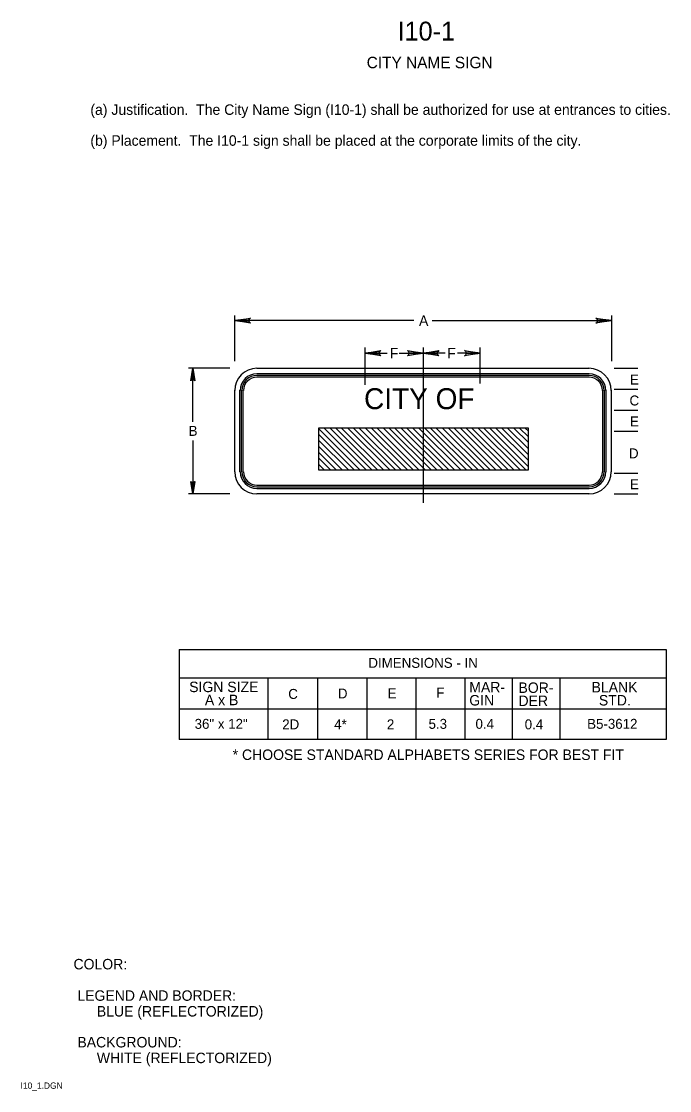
# Model space of a CAD drawing. Extents: x 0.013 to 0.167, y 0.004 to 0.259.
import ezdxf

# ---------------------------------------------------------------- set-up
doc = ezdxf.new("R2010")
doc.units = 0
for name, color, linetype in [('1', 7, 'Continuous'), ('2', 7, 'Continuous'), ('3', 7, 'Continuous')]:
    doc.layers.add(name, color=color, linetype=linetype)

# ---------------------------------------------------------------- blocks, each defined once
blk = doc.blocks.new('RARROW')
at = {"layer": '3'}
for p, q in [((-2.156, 0.285), (-2.2665, 0.384625)), ((-2.2665, 0.384625), (0, 0)), ((0, 0), (-2.2665, -0.379125)), ((-2.156, 0.285), (-2.075625, 0.12075)), ((0, 0), (-2.156, 0.285)), ((-2.14975, -0.2705), (0, 0)), ((-2.075625, 0.12075), (0, 0)), ((0, 0), (-2.074, -0.108)), ((-2.2665, -0.379125), (-2.14975, -0.2705)), ((-2.074, -0.108), (-2.14975, -0.2705))]:
    blk.add_line(p, q, dxfattribs=at)

msp = doc.modelspace()

# ---------------------------------------------------------------- linework, layer by layer
at = {"layer": '1'}
msp.add_line((0.10862, 0.18135), (0.10862, 0.14425), dxfattribs=at)
at = {"layer": '3'}
for p, q in [((0.06363, 0.17804), (0.06363, 0.189)), ((0.15363, 0.17804), (0.15363, 0.189)), ((0.10637, 0.18775), (0.06363, 0.18775)), ((0.11075, 0.18775), (0.15363, 0.18775)), ((0.09475, 0.17245), (0.09475, 0.18134)), ((0.12225, 0.17277), (0.12225, 0.18134)), ((0.09475, 0.17997), (0.1, 0.17997)), ((0.10289, 0.17997), (0.10862, 0.17997)), ((0.10862, 0.18059), (0.10862, 0.17959)), ((0.11388, 0.17997), (0.10862, 0.17997)), ((0.12225, 0.17997), (0.1168, 0.17997)), ((0.06248, 0.17638), (0.05262, 0.17638)), ((0.05362, 0.16362), (0.05362, 0.17638)), ((0.06888, 0.17638), (0.14825, 0.17638)), ((0.15425, 0.17638), (0.15988, 0.17638)), ((0.06888, 0.17513), (0.14825, 0.17513)), ((0.06888, 0.17472), (0.14825, 0.17472)), ((0.06888, 0.17432), (0.14825, 0.17432)), ((0.06363, 0.15163), (0.06363, 0.17112)), ((0.06488, 0.15163), (0.06488, 0.17112)), ((0.06528, 0.15163), (0.06528, 0.17112)), ((0.06567, 0.15163), (0.06567, 0.17112)), ((0.15145, 0.17112), (0.15145, 0.15163)), ((0.15185, 0.17112), (0.15185, 0.15163)), ((0.15225, 0.17112), (0.15225, 0.15163)), ((0.1535, 0.17112), (0.1535, 0.15163)), ((0.15425, 0.17137), (0.15988, 0.17137)), ((0.15425, 0.16637), (0.15988, 0.16637)), ((0.08363, 0.162), (0.0935, 0.15213)), ((0.085, 0.16212), (0.095, 0.15213)), ((0.08638, 0.16212), (0.09638, 0.15213)), ((0.08775, 0.16212), (0.09775, 0.15213)), ((0.08912, 0.16212), (0.09913, 0.15213)), ((0.09062, 0.16212), (0.10063, 0.15213)), ((0.092, 0.16212), (0.102, 0.15213)), ((0.09337, 0.16212), (0.10338, 0.15213)), ((0.09488, 0.16212), (0.10487, 0.15213)), ((0.09625, 0.16212), (0.10625, 0.15213)), ((0.09763, 0.16212), (0.10762, 0.15213)), ((0.09913, 0.16212), (0.10912, 0.15213)), ((0.1005, 0.16212), (0.1105, 0.15213)), ((0.10188, 0.16212), (0.11188, 0.15213)), ((0.10338, 0.16212), (0.11338, 0.15213)), ((0.10475, 0.16212), (0.11475, 0.15213)), ((0.10612, 0.16212), (0.11613, 0.15213)), ((0.10762, 0.16212), (0.11763, 0.15213)), ((0.109, 0.16212), (0.119, 0.15213)), ((0.11038, 0.16212), (0.12037, 0.15213)), ((0.11175, 0.16212), (0.12175, 0.15213)), ((0.11325, 0.16212), (0.12325, 0.15213)), ((0.11463, 0.16212), (0.12462, 0.15213)), ((0.116, 0.16212), (0.126, 0.15213)), ((0.1175, 0.16212), (0.1275, 0.15213)), ((0.11888, 0.16212), (0.12887, 0.15213)), ((0.12025, 0.16212), (0.13025, 0.15213)), ((0.12175, 0.16212), (0.13175, 0.15213)), ((0.12312, 0.16212), (0.13312, 0.15213)), ((0.1245, 0.16212), (0.13375, 0.15288)), ((0.126, 0.16212), (0.13375, 0.15438)), ((0.12738, 0.16212), (0.13375, 0.15575)), ((0.12875, 0.16212), (0.13375, 0.15713)), ((0.13025, 0.16212), (0.13375, 0.15863)), ((0.13162, 0.16212), (0.13375, 0.16)), ((0.133, 0.16212), (0.13375, 0.16137)), ((0.15425, 0.16137), (0.15988, 0.16137)), ((0.05362, 0.15913), (0.05362, 0.14638)), ((0.08363, 0.16062), (0.09212, 0.15213)), ((0.08363, 0.15925), (0.09075, 0.15213)), ((0.08363, 0.15775), (0.08925, 0.15213)), ((0.08363, 0.15638), (0.08788, 0.15213)), ((0.08363, 0.155), (0.0865, 0.15213)), ((0.08363, 0.1535), (0.085, 0.15213)), ((0.08363, 0.15213), (0.08363, 0.15213)), ((0.15425, 0.15138), (0.15988, 0.15138)), ((0.14825, 0.14843), (0.06888, 0.14843)), ((0.06248, 0.14638), (0.05262, 0.14638)), ((0.14825, 0.14803), (0.06888, 0.14803)), ((0.14825, 0.14763), (0.06888, 0.14763)), ((0.14825, 0.14638), (0.06888, 0.14638)), ((0.15425, 0.14638), (0.15988, 0.14638)), ((0.05038, 0.10925), (0.16662, 0.10925)), ((0.05038, 0.10925), (0.05038, 0.08775)), ((0.16662, 0.10925), (0.16662, 0.08775)), ((0.16662, 0.10238), (0.05038, 0.10238)), ((0.07153, 0.10238), (0.07153, 0.08776)), ((0.08338, 0.10238), (0.08338, 0.08775)), ((0.09513, 0.10238), (0.09513, 0.08775)), ((0.10687, 0.10238), (0.10687, 0.08775)), ((0.11853, 0.10238), (0.11853, 0.08776)), ((0.1299, 0.10238), (0.1299, 0.08776)), ((0.14128, 0.10238), (0.14128, 0.08776)), ((0.16662, 0.095), (0.05038, 0.095)), ((0.16662, 0.08775), (0.05038, 0.08775))]:
    msp.add_line(p, q, dxfattribs=at)
msp.add_lwpolyline([(0.13375, 0.16212), (0.08363, 0.16212), (0.08363, 0.15213), (0.13375, 0.15213)], close=True, dxfattribs=at)
for centre, radius, start, end in [((0.06893, 0.17108), 0.0053, 90, 180), ((0.1482, 0.17108), 0.0053, 0, 90), ((0.06893, 0.17108), 0.004, 90, 180), ((0.06893, 0.17108), 0.0036, 90, 180), ((0.06893, 0.17108), 0.0032, 90, 180), ((0.1482, 0.17108), 0.004, 0, 90), ((0.1482, 0.17108), 0.0036, 0, 90), ((0.1482, 0.17108), 0.0032, 0, 90), ((0.06893, 0.15168), 0.0053, 180, 270), ((0.06893, 0.15168), 0.004, 180, 270), ((0.06893, 0.15168), 0.0036, 180, 270), ((0.06893, 0.15168), 0.0032, 180, 270), ((0.1482, 0.15168), 0.0053, 270, 0), ((0.1482, 0.15168), 0.004, 270, 0), ((0.1482, 0.15168), 0.0036, 270, 0), ((0.1482, 0.15168), 0.0032, 270, 0)]:
    msp.add_arc(centre, radius, start, end, dxfattribs=at)

# ---------------------------------------------------------------- block references
for p, xscale, yscale, rotation in [((0.06363, 0.18775), 0.0016545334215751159, 0.0016366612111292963, 180), ((0.09475, 0.17997), 0.0016545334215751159, 0.0016366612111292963, 180), ((0.10862, 0.17997), 0.0016545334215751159, 0.0016366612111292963, 180), ((0.05362, 0.17638), 0.0013236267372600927, 0.001309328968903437, 90), ((0.05362, 0.14638), 0.0013236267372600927, 0.001309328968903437, -90)]:
    msp.add_blockref('RARROW', p, dxfattribs=dict(at, xscale=xscale, yscale=yscale, rotation=rotation))
at = {"layer": '3', "xscale": 0.0016545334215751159, "yscale": 0.0016366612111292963}
for p in [(0.15363, 0.18775), (0.10862, 0.17997), (0.12225, 0.17997)]:
    msp.add_blockref('RARROW', p, dxfattribs=at)

# ---------------------------------------------------------------- texts
at = {"layer": '1'}
for s, height, p in [('I10-1', 0.0045, (0.1025, 0.25462)), ('CITY NAME SIGN', 0.0027503, (0.09513, 0.248)), ('COLOR:', 0.0025, (0.02513, 0.03288)), (' LEGEND AND BORDER:', 0.0024998, (0.02513, 0.02538)), ('      BLUE (REFLECTORIZED)', 0.0024998, (0.02513, 0.02163)), (' BACKGROUND:', 0.0024998, (0.02513, 0.01425)), ('      WHITE (REFLECTORIZED)', 0.0024998, (0.02513, 0.0105)), ('I10_1.DGN', 0.0015, (0.0125, 0.00438))]:
    msp.add_text(s, height=height, dxfattribs=at).set_placement(p)
at = {"layer": '2'}
for s, height, p in [('   (a) Justification.  The City Name Sign (I10-1) shall be authorized for use at entrances to cities.', 0.00249975, (0.02637, 0.23688)), ('   (b) Placement.  The I10-1 sign shall be placed at the corporate limits of the city.', 0.0024998, (0.02637, 0.2295))]:
    msp.add_text(s, height=height, dxfattribs=at).set_placement(p)
at = {"layer": '3'}
for s, height, p in [('A', 0.0025, (0.10762, 0.1865)), ('F', 0.0025, (0.10063, 0.17872)), ('F', 0.0025, (0.11438, 0.17872)), ('E', 0.00238, (0.158, 0.1725)), ('CITY OF', 0.005, (0.0945, 0.16662)), ('C', 0.00238, (0.15788, 0.1675)), ('E', 0.00238, (0.158, 0.1625)), ('B', 0.00238, (0.05262, 0.16025)), ('D', 0.00238, (0.15775, 0.15488)), ('E', 0.00238, (0.158, 0.1475)), ('DIMENSIONS - IN', 0.0023752, (0.09554, 0.10487)), ('SIGN SIZE', 0.0025, (0.05275, 0.09907)), ('C', 0.00238, (0.0764, 0.09745)), ('D', 0.00238, (0.08825, 0.09755)), ('E', 0.00238, (0.10014, 0.0976)), ('F', 0.00238, (0.11175, 0.09775)), ('MAR-', 0.0025, (0.11963, 0.099)), ('BOR-', 0.0025, (0.13137, 0.09888)), ('BLANK', 0.0025, (0.14882, 0.099)), ('A x B', 0.0025, (0.0565, 0.09595)), ('GIN', 0.0025, (0.11963, 0.09588)), ('DER', 0.0025, (0.13137, 0.09575)), ('STD.', 0.0025, (0.15057, 0.09588)), ('36" x 12"', 0.002375, (0.05405, 0.09031)), ('2D', 0.002375, (0.07497, 0.09019)), ('4*', 0.002375, (0.08737, 0.09019)), ('2', 0.00238, (0.09995, 0.09019)), ('5.3', 0.002375, (0.1099, 0.09031)), ('0.4', 0.002375, (0.12111, 0.09031)), ('0.4', 0.002375, (0.13286, 0.09019)), ('B5-3612', 0.002375, (0.14777, 0.09031)), ('* CHOOSE STANDARD ALPHABETS SERIES FOR BEST FIT', 0.0024998, (0.06313, 0.08288))]:
    msp.add_text(s, height=height, dxfattribs=at).set_placement(p)

doc.saveas('drawing.dxf')
